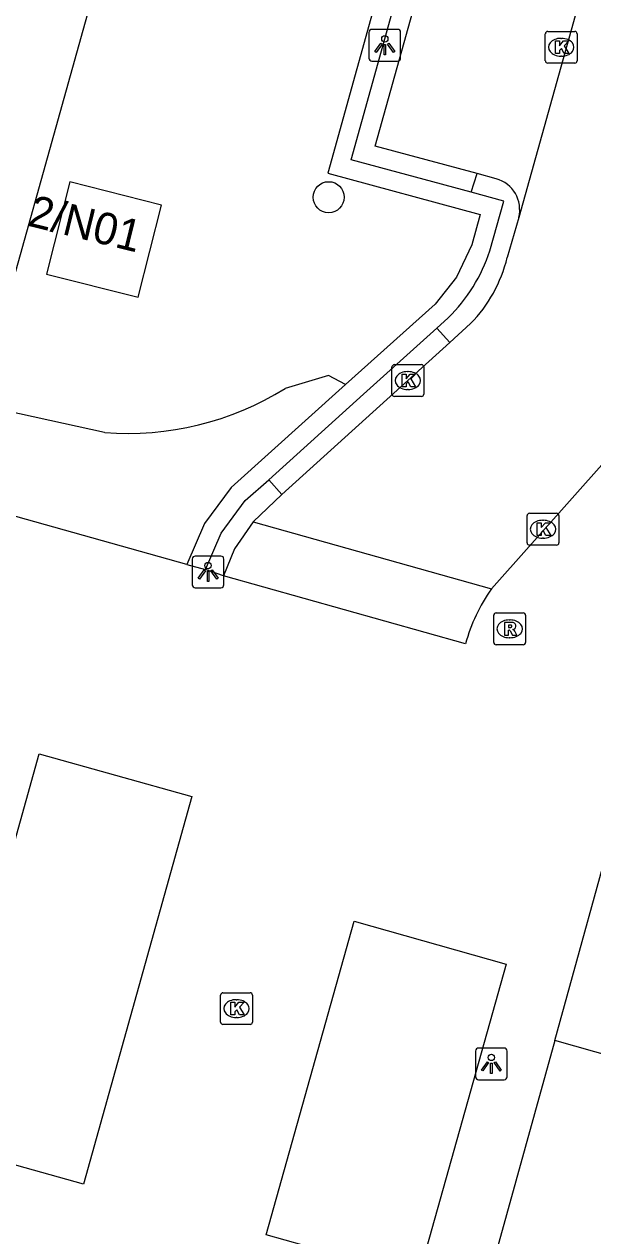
# Model space of a CAD drawing. Extents: x 158087 to 159494, y 382905 to 383981.
# Drawn here: x 158698.79 to 158716.68, y 383259.48 to 383297.57 of the extents above; entities that cross this region are included whole.
import ezdxf

# ---------------------------------------------------------------- set-up
doc = ezdxf.new("R2010")
doc.units = 0
for name, color, linetype in [('IMGEO_Boom', 7, 'Continuous'), ('IMGEO_Groenvoorziening', 7, 'Continuous'), ('IMGEO_Haag', 7, 'Continuous'), ('IMGEO_Kolk', 7, 'Continuous'), ('IMGEO_Lichtpunt', 7, 'Continuous'), ('IMGEO_Pand', 7, 'Continuous'), ('IMGEO_Pand_nummerreeks', 7, 'Continuous'), ('IMGEO_Rijbaan_lokaal_open', 7, 'Continuous'), ('IMGEO_Rioolput', 7, 'Continuous'), ('IMGEO_Voetpad_open', 7, 'Continuous')]:
    doc.layers.add(name, color=color, linetype=linetype)

msp = doc.modelspace()

# ---------------------------------------------------------------- linework, layer by layer
at = {"layer": 'IMGEO_Boom'}
msp.add_circle((158708.374, 383292.129), 0.489, dxfattribs=at)
at = {"layer": 'IMGEO_Groenvoorziening'}
for points in [[(158708.905, 383286.24), (158708.372, 383286.529), (158707.006, 383286.118)], [(158701.326, 383284.735), (158697.345, 383285.602)]]:
    msp.add_lwpolyline(points, dxfattribs=at)
msp.add_arc((158702.056, 383294.094), 9.388, 265.5431, 301.8258, dxfattribs=at)
at = {"layer": 'IMGEO_Haag'}
for points in [[(158715.651, 383319.137), (158708.346, 383292.883), (158713.145, 383291.584), (158712.877, 383290.631), (158712.4, 383289.615), (158711.72, 383288.771), (158708.905, 383286.24)], [(158708.905, 383286.24), (158705.305, 383283.005), (158704.465, 383281.869), (158703.916, 383280.587)]]:
    msp.add_lwpolyline(points, dxfattribs=at)
at = {"layer": 'IMGEO_Kolk'}
for p, q in [((158715.19, 383296.418), (158715.19, 383297.27)), ((158715.265, 383297.344), (158716.117, 383297.344)), ((158716.191, 383297.27), (158716.191, 383296.418)), ((158715.678, 383297.124), (158715.703, 383297.124)), ((158715.701, 383296.564), (158715.676, 383296.564)), ((158716.117, 383296.344), (158715.265, 383296.344)), ((158710.365, 383285.94), (158710.365, 383286.792)), ((158710.44, 383286.866), (158711.292, 383286.866)), ((158710.853, 383286.646), (158710.878, 383286.646)), ((158711.366, 383286.792), (158711.366, 383285.94)), ((158711.292, 383285.866), (158710.44, 383285.866)), ((158710.876, 383286.086), (158710.851, 383286.086)), ((158714.617, 383281.266), (158714.617, 383282.118)), ((158714.692, 383282.192), (158715.544, 383282.192)), ((158715.618, 383282.118), (158715.618, 383281.266)), ((158715.105, 383281.972), (158715.13, 383281.972)), ((158715.128, 383281.412), (158715.103, 383281.412)), ((158715.544, 383281.192), (158714.692, 383281.192)), ((158704.974, 383266.195), (158704.974, 383267.047)), ((158705.049, 383267.121), (158705.901, 383267.121)), ((158705.462, 383266.901), (158705.487, 383266.901)), ((158705.975, 383267.047), (158705.975, 383266.195)), ((158705.901, 383266.121), (158705.049, 383266.121)), ((158705.485, 383266.341), (158705.46, 383266.341))]:
    msp.add_line(p, q, dxfattribs=at)
for points in [[(158715.19, 383296.418), (158715.19, 383297.27)], [(158715.265, 383297.344), (158716.117, 383297.344)], [(158716.191, 383297.27), (158716.191, 383296.418)], [(158715.511, 383297.044), (158715.634, 383297.044), (158715.634, 383296.893), (158715.764, 383297.044), (158715.928, 383297.044), (158715.782, 383296.893), (158715.935, 383296.644), (158715.783, 383296.644), (158715.698, 383296.808), (158715.634, 383296.741), (158715.634, 383296.644), (158715.511, 383296.644), (158715.511, 383297.044)], [(158716.117, 383296.344), (158715.265, 383296.344)], [(158710.365, 383285.94), (158710.365, 383286.792)], [(158710.44, 383286.866), (158711.292, 383286.866)], [(158710.686, 383286.566), (158710.809, 383286.566), (158710.809, 383286.415), (158710.939, 383286.566), (158711.103, 383286.566), (158710.957, 383286.415), (158711.11, 383286.166), (158710.958, 383286.166), (158710.873, 383286.33), (158710.809, 383286.263), (158710.809, 383286.166), (158710.686, 383286.166), (158710.686, 383286.566)], [(158711.366, 383286.792), (158711.366, 383285.94)], [(158711.292, 383285.866), (158710.44, 383285.866)], [(158714.617, 383281.266), (158714.617, 383282.118)], [(158714.692, 383282.192), (158715.544, 383282.192)], [(158715.618, 383282.118), (158715.618, 383281.266)], [(158714.938, 383281.892), (158715.061, 383281.892), (158715.061, 383281.741), (158715.191, 383281.892), (158715.355, 383281.892), (158715.209, 383281.741), (158715.362, 383281.492), (158715.21, 383281.492), (158715.125, 383281.656), (158715.061, 383281.589), (158715.061, 383281.492), (158714.938, 383281.492), (158714.938, 383281.892)], [(158715.544, 383281.192), (158714.692, 383281.192)], [(158704.974, 383266.195), (158704.974, 383267.047)], [(158705.049, 383267.121), (158705.901, 383267.121)], [(158705.295, 383266.821), (158705.418, 383266.821), (158705.418, 383266.67), (158705.548, 383266.821), (158705.712, 383266.821), (158705.566, 383266.67), (158705.719, 383266.421), (158705.567, 383266.421), (158705.482, 383266.585), (158705.418, 383266.518), (158705.418, 383266.421), (158705.295, 383266.421), (158705.295, 383266.821)], [(158705.975, 383267.047), (158705.975, 383266.195)], [(158705.901, 383266.121), (158705.049, 383266.121)]]:
    msp.add_lwpolyline(points, dxfattribs=at)
for centre, start, end in [((158715.267, 383297.268), 91.552, 178.448), ((158715.267, 383297.268), 91.552, 178.448), ((158716.115, 383297.268), 1.552, 88.448), ((158716.115, 383297.268), 1.552, 88.448), ((158715.267, 383296.42), 181.552, 268.448), ((158715.267, 383296.42), 181.552, 268.448), ((158716.115, 383296.42), 271.552, 358.448), ((158716.115, 383296.42), 271.552, 358.448), ((158710.442, 383286.79), 91.552, 178.448), ((158710.442, 383286.79), 91.552, 178.448), ((158711.29, 383286.79), 1.552, 88.448), ((158711.29, 383286.79), 1.552, 88.448), ((158710.442, 383285.942), 181.552, 268.448), ((158710.442, 383285.942), 181.552, 268.448), ((158711.29, 383285.942), 271.552, 358.448), ((158711.29, 383285.942), 271.552, 358.448), ((158714.694, 383282.116), 91.552, 178.448), ((158714.694, 383282.116), 91.552, 178.448), ((158715.542, 383282.116), 1.552, 88.448), ((158715.542, 383282.116), 1.552, 88.448), ((158714.694, 383281.268), 181.552, 268.448), ((158714.694, 383281.268), 181.552, 268.448), ((158715.542, 383281.268), 271.552, 358.448), ((158715.542, 383281.268), 271.552, 358.448), ((158705.051, 383267.045), 91.552, 178.448), ((158705.051, 383267.045), 91.552, 178.448), ((158705.899, 383267.045), 1.552, 88.448), ((158705.899, 383267.045), 1.552, 88.448), ((158705.051, 383266.197), 181.552, 268.448), ((158705.051, 383266.197), 181.552, 268.448), ((158705.899, 383266.197), 271.552, 358.448), ((158705.899, 383266.197), 271.552, 358.448)]:
    msp.add_arc(centre, 0.0765, start, end, dxfattribs=at)
for centre, major_axis, ratio, start_param, end_param in [((158715.677, 383296.844), (-0.387, 0.002), 0.722429, 4.712389, 7.853982), ((158715.702, 383296.844), (-0.39, 0.002), 0.717154, 1.570796, 4.712389), ((158710.852, 383286.366), (-0.387, 0.002), 0.722429, 4.712389, 7.853982), ((158710.877, 383286.366), (-0.39, 0.002), 0.717154, 1.570796, 4.712389), ((158715.104, 383281.692), (-0.387, 0.002), 0.722429, 4.712389, 7.853982), ((158715.129, 383281.692), (-0.39, 0.002), 0.717154, 1.570796, 4.712389), ((158705.461, 383266.621), (-0.387, 0.002), 0.722429, 4.712389, 7.853982), ((158705.486, 383266.621), (-0.39, 0.002), 0.717154, 1.570796, 4.712389)]:
    msp.add_ellipse(centre, major_axis=major_axis, ratio=ratio, start_param=start_param, end_param=end_param, dxfattribs=at)
at = {"layer": 'IMGEO_Lichtpunt'}
for p, q in [((158709.642, 383297.31), (158709.642, 383296.503)), ((158709.642, 383297.31), (158709.642, 383296.503)), ((158710.544, 383297.405), (158709.736, 383297.405)), ((158710.544, 383297.405), (158709.736, 383297.405)), ((158710.638, 383296.503), (158710.638, 383297.31)), ((158710.638, 383296.503), (158710.638, 383297.31)), ((158709.736, 383296.409), (158710.544, 383296.409)), ((158709.736, 383296.409), (158710.544, 383296.409)), ((158704.983, 383280.847), (158704.175, 383280.847)), ((158704.983, 383280.847), (158704.175, 383280.847)), ((158704.081, 383280.752), (158704.081, 383279.945)), ((158704.081, 383280.752), (158704.081, 383279.945)), ((158705.077, 383279.945), (158705.077, 383280.752)), ((158705.077, 383279.945), (158705.077, 383280.752)), ((158704.175, 383279.851), (158704.983, 383279.851)), ((158704.175, 383279.851), (158704.983, 383279.851)), ((158712.994, 383265.286), (158712.994, 383264.479)), ((158712.994, 383265.286), (158712.994, 383264.479)), ((158713.896, 383265.381), (158713.088, 383265.381)), ((158713.896, 383265.381), (158713.088, 383265.381)), ((158713.99, 383264.479), (158713.99, 383265.286)), ((158713.99, 383264.479), (158713.99, 383265.286)), ((158713.088, 383264.385), (158713.896, 383264.385)), ((158713.088, 383264.385), (158713.896, 383264.385))]:
    msp.add_line(p, q, dxfattribs=at)
for points in [[(158710.016, 383296.974), (158710.055, 383296.946), (158709.867, 383296.684), (158709.829, 383296.711), (158710.016, 383296.974)], [(158710.118, 383296.926), (158710.165, 383296.926), (158710.165, 383296.604), (158710.118, 383296.604), (158710.118, 383296.926)], [(158710.228, 383296.946), (158710.266, 383296.973), (158710.453, 383296.711), (158710.414, 383296.683), (158710.228, 383296.946)], [(158704.455, 383280.416), (158704.494, 383280.388), (158704.306, 383280.126), (158704.268, 383280.153), (158704.455, 383280.416)], [(158704.557, 383280.368), (158704.604, 383280.368), (158704.604, 383280.046), (158704.557, 383280.046), (158704.557, 383280.368)], [(158704.667, 383280.388), (158704.705, 383280.415), (158704.892, 383280.153), (158704.853, 383280.125), (158704.667, 383280.388)], [(158713.368, 383264.95), (158713.407, 383264.922), (158713.219, 383264.66), (158713.181, 383264.687), (158713.368, 383264.95)], [(158713.47, 383264.902), (158713.517, 383264.902), (158713.517, 383264.58), (158713.47, 383264.58), (158713.47, 383264.902)], [(158713.58, 383264.922), (158713.618, 383264.949), (158713.805, 383264.687), (158713.766, 383264.659), (158713.58, 383264.922)]]:
    msp.add_lwpolyline(points, dxfattribs=at)
for centre in [(158710.141, 383297.108), (158704.58, 383280.55), (158713.493, 383265.084)]:
    msp.add_circle(centre, 0.0994, dxfattribs=at)
for centre, start, end in [((158709.736, 383297.31), 90, 180), ((158709.736, 383297.31), 90, 180), ((158710.544, 383297.31), 0, 90), ((158710.544, 383297.31), 0, 90), ((158709.736, 383296.503), 180, 270), ((158709.736, 383296.503), 180, 270), ((158710.544, 383296.503), 270, 0), ((158710.544, 383296.503), 270, 360), ((158704.175, 383280.752), 90, 180), ((158704.175, 383280.752), 90, 180), ((158704.983, 383280.752), 0, 90), ((158704.983, 383280.752), 0, 90), ((158704.175, 383279.945), 180, 270), ((158704.175, 383279.945), 180, 270), ((158704.983, 383279.945), 270, 0), ((158704.983, 383279.945), 270, 360), ((158713.088, 383265.286), 90, 180), ((158713.088, 383265.286), 90, 180), ((158713.896, 383265.286), 0, 90), ((158713.896, 383265.286), 0, 90), ((158713.088, 383264.479), 180, 270), ((158713.088, 383264.479), 180, 270), ((158713.896, 383264.479), 270, 0), ((158713.896, 383264.479), 270, 360)]:
    msp.add_arc(centre, 0.0946, start, end, dxfattribs=at)
at = {"layer": 'IMGEO_Pand'}
for points in [[(158702.377, 383288.983), (158703.111, 383291.882), (158700.229, 383292.611), (158699.495, 383289.712), (158702.377, 383288.983)], [(158715.488, 383265.62), (158717.6, 383273.245)], [(158715.488, 383265.62), (158713.33, 383257.83)], [(158724.45, 383263.079), (158715.488, 383265.62)]]:
    msp.add_lwpolyline(points, dxfattribs=at)
at = {"layer": 'IMGEO_Rijbaan_lokaal_open'}
for points in [[(158721.142, 383315.77), (158714.354, 383291.491)], [(158714.354, 383291.491), (158713.992, 383290.23)], [(158712.839, 383288.156), (158712.19, 383287.558)], [(158712.19, 383287.558), (158706.901, 383282.787)], [(158713.492, 383279.816), (158718.325, 383285.237)], [(158706.901, 383282.787), (158706, 383281.923)], [(158706, 383281.923), (158705.414, 383281.076), (158705.06, 383280.231)], [(158706, 383281.923), (158713.492, 383279.816)], [(158712.681, 383278.089), (158705.06, 383280.231)]]:
    msp.add_lwpolyline(points, dxfattribs=at)
for centre, radius, start, end in [((158709.636, 383291.294), 4.484, 315.5852, 346.2728), ((158717.932, 383276.677), 5.438, 144.7412, 164.9493)]:
    msp.add_arc(centre, radius, start, end, dxfattribs=at)
at = {"layer": 'IMGEO_Rioolput'}
for p, q in [((158713.568, 383278.134), (158713.568, 383278.986)), ((158713.643, 383279.06), (158714.495, 383279.06)), ((158714.569, 383278.986), (158714.569, 383278.134)), ((158714.056, 383278.84), (158714.081, 383278.84)), ((158714.079, 383278.28), (158714.054, 383278.28)), ((158714.495, 383278.06), (158713.643, 383278.06))]:
    msp.add_line(p, q, dxfattribs=at)
for points in [[(158713.568, 383278.134), (158713.568, 383278.986)], [(158713.643, 383279.06), (158714.495, 383279.06)], [(158714.569, 383278.986), (158714.569, 383278.134)], [(158714.157, 383278.758), (158713.905, 383278.76), (158713.905, 383278.36)], [(158714.083, 383278.679), (158714.029, 383278.679), (158714.029, 383278.598)], [(158714.029, 383278.598), (158714.081, 383278.598)], [(158713.905, 383278.36), (158714.029, 383278.36), (158714.029, 383278.522), (158714.04, 383278.522)], [(158714.087, 383278.493), (158714.158, 383278.36), (158714.298, 383278.36), (158714.233, 383278.486)], [(158714.495, 383278.06), (158713.643, 383278.06)]]:
    msp.add_lwpolyline(points, dxfattribs=at)
for centre, radius, start, end in [((158713.645, 383278.984), 0.0765, 91.552, 178.448), ((158713.645, 383278.984), 0.0765, 91.552, 178.448), ((158714.493, 383278.984), 0.0765, 1.552, 88.448), ((158714.493, 383278.984), 0.0765, 1.552, 88.448), ((158714.065, 383278.787), 0.19, 274.7715, 282.9687), ((158714.089, 383278.583), 0.0964, 77.0061, 93.1865), ((158714.103, 383278.64), 0.0378, 276.6634, 79.6772), ((158714.156, 383278.648), 0.109, 350.3612, 89.416), ((158714.154, 383278.648), 0.112, 277.5842, 350.9817), ((158714.039, 383278.469), 0.0533, 26.0293, 88.6989), ((158714.138, 383278.433), 0.108, 29.5134, 73.7905), ((158713.645, 383278.136), 0.0765, 181.552, 268.448), ((158713.645, 383278.136), 0.0765, 181.552, 268.448), ((158714.493, 383278.136), 0.0765, 271.552, 358.448), ((158714.493, 383278.136), 0.0765, 271.552, 358.448)]:
    msp.add_arc(centre, radius, start, end, dxfattribs=at)
for centre, major_axis, ratio, start_param, end_param in [((158714.055, 383278.56), (-0.387, 0.002), 0.722429, 4.712389, 7.853982), ((158714.08, 383278.56), (-0.39, 0.002), 0.717154, 1.570796, 4.712389)]:
    msp.add_ellipse(centre, major_axis=major_axis, ratio=ratio, start_param=start_param, end_param=end_param, dxfattribs=at)
at = {"layer": 'IMGEO_Voetpad_open'}
for points in [[(158712.858, 383292.286), (158709.086, 383293.304), (158715.763, 383317.299)], [(158713.041, 383292.873), (158709.84, 383293.736), (158716.38, 383317.125)], [(158697.345, 383285.602), (158700.848, 383298.094)], [(158712.858, 383292.286), (158713.041, 383292.873)], [(158713.646, 383292.709), (158713.041, 383292.873)], [(158713.449, 383290.447), (158713.886, 383292.005), (158712.858, 383292.286)], [(158711.776, 383288.016), (158712.136, 383288.337)], [(158706.491, 383283.248), (158709.467, 383285.933), (158711.776, 383288.016)], [(158711.776, 383288.016), (158712.19, 383287.558)], [(158704.499, 383280.425), (158704.989, 383281.568), (158705.749, 383282.597), (158706.491, 383283.248)], [(158706.901, 383282.787), (158706.491, 383283.248)], [(158703.916, 383280.587), (158696.463, 383282.664)], [(158703.916, 383280.587), (158704.499, 383280.425)], [(158705.06, 383280.231), (158704.499, 383280.425)], [(158699.27, 383274.633), (158704.071, 383273.29), (158700.662, 383261.103), (158695.861, 383262.446), (158699.27, 383274.633)], [(158709.174, 383269.365), (158713.954, 383268.023), (158711.189, 383258.167), (158706.409, 383259.508), (158709.174, 383269.365)]]:
    msp.add_lwpolyline(points, dxfattribs=at)
for centre, radius, start, end in [((158713.373, 383291.736), 1.011, 345.9856, 74.3516), ((158708.419, 383292.113), 5.298, 314.5439, 341.6702)]:
    msp.add_arc(centre, radius, start, end, dxfattribs=at)

# ---------------------------------------------------------------- texts
at = {"layer": 'IMGEO_Pand_nummerreeks'}
msp.add_text('2/N01', height=1, rotation=346.2005, dxfattribs=at).set_placement((158698.868, 383291.242))

doc.saveas('drawing.dxf')
